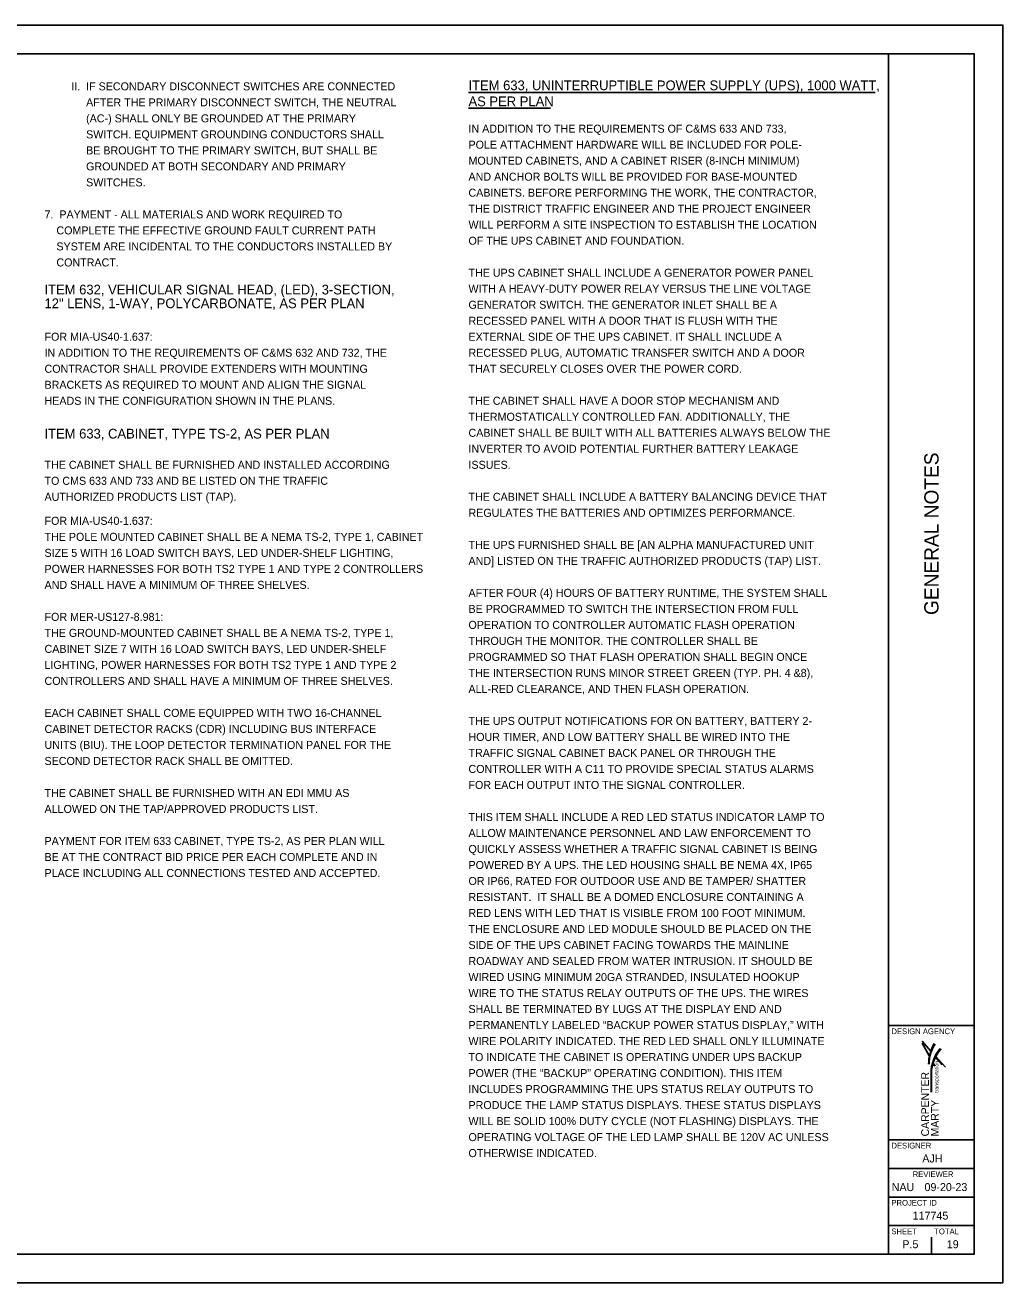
# Model space of a CAD drawing. Extents: x -57 to 92, y -15 to 47.
# Drawn here: x 75.2 to 92.31, y 25.1 to 47.1 of the extents above; entities that cross this region are included whole.
import ezdxf

# ---------------------------------------------------------------- set-up
doc = ezdxf.new("R2010")
doc.units = 0
for name, color, linetype in [('SH_Border', 7, 'Continuous'), ('SH_Cut_Line', 7, 'Continuous'), ('SH_Data', 7, 'Continuous'), ('SH_Text', 7, 'Continuous')]:
    doc.layers.add(name, color=color, linetype=linetype)

msp = doc.modelspace()

# ---------------------------------------------------------------- linework, layer by layer
at = {"layer": 'SH_Border'}
for p, q in [((90.307, 25.604), (90.307, 46.604)), ((90.307, 29.604), (91.807, 29.604)), ((90.307, 27.604), (91.807, 27.604)), ((90.307, 27.104), (91.807, 27.104)), ((90.307, 26.604), (91.807, 26.604)), ((90.307, 26.104), (91.807, 26.104))]:
    msp.add_line(p, q, dxfattribs=at)
msp.add_lwpolyline([(59.807, 46.604), (91.807, 46.604), (91.807, 25.604), (59.807, 25.604)], close=True, dxfattribs=at)
at = {"layer": 'SH_Cut_Line'}
msp.add_lwpolyline([(58.307, 25.104), (92.307, 25.104), (92.307, 47.104), (58.307, 47.104)], close=True, dxfattribs=at)
at = {"layer": 'SH_Data'}
for p, q in [((91.057, 28.604), (91.057, 28.604)), ((90.682, 25.779), (90.682, 25.779)), ((91.057, 25.604), (91.057, 25.904))]:
    msp.add_line(p, q, dxfattribs=at)
at = {"layer": 'SH_Text'}
for p, q in [((82.955, 45.923), (90.07, 45.923)), ((82.955, 45.652), (84.391, 45.652)), ((91.016, 29.079), (90.897, 29.295)), ((91.247, 28.915), (91.13, 29.054)), ((91.135, 29.064), (91.301, 28.879)), ((91.106, 28.903), (91.085, 28.943)), ((91.116, 28.896), (91.087, 28.949)), ((91.05, 28.44), (91.05, 28.767)), ((91.057, 28.44), (91.057, 28.767))]:
    msp.add_line(p, q, dxfattribs=at)
for points in [[(91.042, 29.167), (90.897, 29.329)], [(90.897, 29.329), (91.039, 29.161)], [(91.016, 29.079), (90.897, 29.295)], [(90.897, 29.294), (91.015, 29.074)]]:
    msp.add_lwpolyline(points, dxfattribs=at)
for centre, radius, start, end in [((91.728, 28.923), 0.721, 149.5704, 179.5529), ((91.669, 28.924), 0.654, 147.1423, 179.6525), ((91.721, 28.767), 0.671, 139.2898, 180.0106), ((91.729, 28.751), 0.672, 138.5126, 178.6075)]:
    msp.add_arc(centre, radius, start, end, dxfattribs=at)

# ---------------------------------------------------------------- texts
at = {"layer": 'SH_Data'}
msp.add_text('GENERAL NOTES', height=0.25, rotation=90, dxfattribs=at).set_placement((91.182, 36.786))
for s, height, p in [('DESIGN AGENCY', 0.1, (90.357, 29.454)), ('DESIGNER', 0.1, (90.357, 27.454)), ('AJH', 0.14, (90.897, 27.209)), ('NAU', 0.14, (90.362, 26.709)), ('REVIEWER', 0.1, (90.729, 26.954)), ('09-20-23', 0.14, (90.936, 26.709)), ('PROJECT ID', 0.1, (90.357, 26.454)), ('117745', 0.14, (90.728, 26.209)), ('SHEET', 0.1, (90.357, 25.954)), ('TOTAL', 0.1, (91.107, 25.954)), ('P.5', 0.14, (90.548, 25.709)), ('19', 0.14, (91.326, 25.709))]:
    msp.add_text(s, height=height, dxfattribs=at).set_placement(p)
at = {"layer": 'SH_Text'}
for s, height, p in [('         II.  IF SECONDARY DISCONNECT SWITCHES ARE CONNECTED', 0.14, (75.535, 45.963)), ('ITEM 633, UNINTERRUPTIBLE POWER SUPPLY (UPS), 1000 WATT,', 0.17, (82.955, 45.966)), ('              AFTER THE PRIMARY DISCONNECT SWITCH, THE NEUTRAL', 0.14, (75.535, 45.683)), ('AS PER PLAN', 0.17, (82.955, 45.686)), ('              (AC-) SHALL ONLY BE GROUNDED AT THE PRIMARY', 0.14, (75.535, 45.403)), ('IN ADDITION TO THE REQUIREMENTS OF C&MS 633 AND 733, ', 0.14, (82.955, 45.223)), ('              SWITCH. EQUIPMENT GROUNDING CONDUCTORS SHALL', 0.14, (75.535, 45.123)), ('              BE BROUGHT TO THE PRIMARY SWITCH, BUT SHALL BE', 0.14, (75.535, 44.843)), ('POLE ATTACHMENT HARDWARE WILL BE INCLUDED FOR POLE-', 0.14, (82.955, 44.943)), ('              GROUNDED AT BOTH SECONDARY AND PRIMARY', 0.14, (75.535, 44.563)), ('MOUNTED CABINETS, AND A CABINET RISER (8-INCH MINIMUM) ', 0.14, (82.955, 44.663)), ('AND ANCHOR BOLTS WILL BE PROVIDED FOR BASE-MOUNTED ', 0.14, (82.955, 44.383)), ('              SWITCHES.', 0.14, (75.535, 44.283)), ('CABINETS. BEFORE PERFORMING THE WORK, THE CONTRACTOR, ', 0.14, (82.955, 44.103)), ('7.  PAYMENT - ALL MATERIALS AND WORK REQUIRED TO', 0.14, (75.535, 43.723)), ('THE DISTRICT TRAFFIC ENGINEER AND THE PROJECT ENGINEER ', 0.14, (82.955, 43.823)), ('    COMPLETE THE EFFECTIVE GROUND FAULT CURRENT PATH', 0.14, (75.535, 43.443)), ('WILL PERFORM A SITE INSPECTION TO ESTABLISH THE LOCATION ', 0.14, (82.955, 43.543)), ('OF THE UPS CABINET AND FOUNDATION.', 0.14, (82.955, 43.263)), ('    SYSTEM ARE INCIDENTAL TO THE CONDUCTORS INSTALLED BY', 0.14, (75.535, 43.163)), ('    CONTRACT.', 0.14, (75.535, 42.883)), ('THE UPS CABINET SHALL INCLUDE A GENERATOR POWER PANEL ', 0.14, (82.955, 42.703)), ('ITEM 632, VEHICULAR SIGNAL HEAD, (LED), 3-SECTION, ', 0.17, (75.535, 42.393)), ('WITH A HEAVY-DUTY POWER RELAY VERSUS THE LINE VOLTAGE ', 0.14, (82.955, 42.423)), ('12" LENS, 1-WAY, POLYCARBONATE, AS PER PLAN', 0.17, (75.535, 42.153)), ('GENERATOR SWITCH. THE GENERATOR INLET SHALL BE A ', 0.14, (82.955, 42.143)), ('RECESSED PANEL WITH A DOOR THAT IS FLUSH WITH THE ', 0.14, (82.955, 41.863)), ('FOR MIA-US40-1.637:', 0.14, (75.535, 41.583)), ('EXTERNAL SIDE OF THE UPS CABINET. IT SHALL INCLUDE A ', 0.14, (82.955, 41.583)), ('IN ADDITION TO THE REQUIREMENTS OF C&MS 632 AND 732, THE ', 0.14, (75.535, 41.303)), ('RECESSED PLUG, AUTOMATIC TRANSFER SWITCH AND A DOOR ', 0.14, (82.955, 41.303)), ('CONTRACTOR SHALL PROVIDE EXTENDERS WITH MOUNTING ', 0.14, (75.535, 41.023)), ('THAT SECURELY CLOSES OVER THE POWER CORD.', 0.14, (82.955, 41.023)), ('BRACKETS AS REQUIRED TO MOUNT AND ALIGN THE SIGNAL ', 0.14, (75.535, 40.743)), ('HEADS IN THE CONFIGURATION SHOWN IN THE PLANS. ', 0.14, (75.535, 40.463)), ('THE CABINET SHALL HAVE A DOOR STOP MECHANISM AND ', 0.14, (82.955, 40.463)), ('THERMOSTATICALLY CONTROLLED FAN. ADDITIONALLY, THE ', 0.14, (82.955, 40.183)), ('ITEM 633, CABINET, TYPE TS-2, AS PER PLAN', 0.17, (75.535, 39.873)), ('CABINET SHALL BE BUILT WITH ALL BATTERIES ALWAYS BELOW THE ', 0.14, (82.955, 39.903)), ('INVERTER TO AVOID POTENTIAL FURTHER BATTERY LEAKAGE ', 0.14, (82.955, 39.623)), ('THE CABINET SHALL BE FURNISHED AND INSTALLED ACCORDING', 0.14, (75.535, 39.343)), ('ISSUES.', 0.14, (82.955, 39.343)), ('TO CMS 633 AND 733 AND BE LISTED ON THE TRAFFIC', 0.14, (75.535, 39.063)), ('AUTHORIZED PRODUCTS LIST (TAP).', 0.14, (75.535, 38.783)), ('THE CABINET SHALL INCLUDE A BATTERY BALANCING DEVICE THAT ', 0.14, (82.955, 38.783)), ('FOR MIA-US40-1.637:', 0.14, (75.535, 38.363)), ('REGULATES THE BATTERIES AND OPTIMIZES PERFORMANCE. ', 0.14, (82.955, 38.503)), ('THE POLE MOUNTED CABINET SHALL BE A NEMA TS-2, TYPE 1, CABINET ', 0.14, (75.535, 38.083)), ('THE UPS FURNISHED SHALL BE [AN ALPHA MANUFACTURED UNIT ', 0.14, (82.955, 37.943)), ('SIZE 5 WITH 16 LOAD SWITCH BAYS, LED UNDER-SHELF LIGHTING, ', 0.14, (75.535, 37.803)), ('POWER HARNESSES FOR BOTH TS2 TYPE 1 AND TYPE 2 CONTROLLERS ', 0.14, (75.535, 37.523)), ('AND] LISTED ON THE TRAFFIC AUTHORIZED PRODUCTS (TAP) LIST.', 0.14, (82.955, 37.663)), ('AND SHALL HAVE A MINIMUM OF THREE SHELVES. ', 0.14, (75.535, 37.243)), ('AFTER FOUR (4) HOURS OF BATTERY RUNTIME, THE SYSTEM SHALL ', 0.14, (82.955, 37.103)), ('BE PROGRAMMED TO SWITCH THE INTERSECTION FROM FULL ', 0.14, (82.955, 36.823)), ('FOR MER-US127-8.981:', 0.14, (75.535, 36.683)), ('THE GROUND-MOUNTED CABINET SHALL BE A NEMA TS-2, TYPE 1,', 0.14, (75.535, 36.403)), ('OPERATION TO CONTROLLER AUTOMATIC FLASH OPERATION ', 0.14, (82.955, 36.543)), ('THROUGH THE MONITOR. THE CONTROLLER SHALL BE ', 0.14, (82.955, 36.263)), ('CABINET SIZE 7 WITH 16 LOAD SWITCH BAYS, LED UNDER-SHELF', 0.14, (75.535, 36.123)), ('PROGRAMMED SO THAT FLASH OPERATION SHALL BEGIN ONCE ', 0.14, (82.955, 35.983)), ('LIGHTING, POWER HARNESSES FOR BOTH TS2 TYPE 1 AND TYPE 2', 0.14, (75.535, 35.843)), ('CONTROLLERS AND SHALL HAVE A MINIMUM OF THREE SHELVES.', 0.14, (75.535, 35.563)), ('THE INTERSECTION RUNS MINOR STREET GREEN (TYP. PH. 4 &8), ', 0.14, (82.955, 35.703)), ('ALL-RED CLEARANCE, AND THEN FLASH OPERATION. ', 0.14, (82.955, 35.423)), ('EACH CABINET SHALL COME EQUIPPED WITH TWO 16-CHANNEL', 0.14, (75.535, 35.003)), ('THE UPS OUTPUT NOTIFICATIONS FOR ON BATTERY, BATTERY 2-', 0.14, (82.955, 34.863)), ('CABINET DETECTOR RACKS (CDR) INCLUDING BUS INTERFACE', 0.14, (75.535, 34.723)), ('UNITS (BIU). THE LOOP DETECTOR TERMINATION PANEL FOR THE', 0.14, (75.535, 34.443)), ('HOUR TIMER, AND LOW BATTERY SHALL BE WIRED INTO THE ', 0.14, (82.955, 34.583)), ('TRAFFIC SIGNAL CABINET BACK PANEL OR THROUGH THE ', 0.14, (82.955, 34.303)), ('SECOND DETECTOR RACK SHALL BE OMITTED.', 0.14, (75.535, 34.163)), ('CONTROLLER WITH A C11 TO PROVIDE SPECIAL STATUS ALARMS ', 0.14, (82.955, 34.023)), ('FOR EACH OUTPUT INTO THE SIGNAL CONTROLLER. ', 0.14, (82.955, 33.743)), ('THE CABINET SHALL BE FURNISHED WITH AN EDI MMU AS', 0.14, (75.535, 33.603)), ('ALLOWED ON THE TAP/APPROVED PRODUCTS LIST.', 0.14, (75.535, 33.323)), ('THIS ITEM SHALL INCLUDE A RED LED STATUS INDICATOR LAMP TO ', 0.14, (82.955, 33.183)), ('ALLOW MAINTENANCE PERSONNEL AND LAW ENFORCEMENT TO ', 0.14, (82.955, 32.903)), ('PAYMENT FOR ITEM 633 CABINET, TYPE TS-2, AS PER PLAN WILL', 0.14, (75.535, 32.763)), ('BE AT THE CONTRACT BID PRICE PER EACH COMPLETE AND IN', 0.14, (75.535, 32.483)), ('QUICKLY ASSESS WHETHER A TRAFFIC SIGNAL CABINET IS BEING ', 0.14, (82.955, 32.623)), ('PLACE INCLUDING ALL CONNECTIONS TESTED AND ACCEPTED.', 0.14, (75.535, 32.203)), ('POWERED BY A UPS. THE LED HOUSING SHALL BE NEMA 4X, IP65 ', 0.14, (82.955, 32.343)), ('OR IP66, RATED FOR OUTDOOR USE AND BE TAMPER/ SHATTER ', 0.14, (82.955, 32.063)), ('RESISTANT.  IT SHALL BE A DOMED ENCLOSURE CONTAINING A ', 0.14, (82.955, 31.783)), ('RED LENS WITH LED THAT IS VISIBLE FROM 100 FOOT MINIMUM. ', 0.14, (82.955, 31.503)), ('THE ENCLOSURE AND LED MODULE SHOULD BE PLACED ON THE ', 0.14, (82.955, 31.223)), ('SIDE OF THE UPS CABINET FACING TOWARDS THE MAINLINE ', 0.14, (82.955, 30.943)), ('ROADWAY AND SEALED FROM WATER INTRUSION. IT SHOULD BE ', 0.14, (82.955, 30.663)), ('WIRED USING MINIMUM 20GA STRANDED, INSULATED HOOKUP ', 0.14, (82.955, 30.383)), ('WIRE TO THE STATUS RELAY OUTPUTS OF THE UPS. THE WIRES ', 0.14, (82.955, 30.103)), ('SHALL BE TERMINATED BY LUGS AT THE DISPLAY END AND ', 0.14, (82.955, 29.823)), ('PERMANENTLY LABELED “BACKUP POWER STATUS DISPLAY,” WITH ', 0.14, (82.955, 29.543)), ('WIRE POLARITY INDICATED. THE RED LED SHALL ONLY ILLUMINATE ', 0.14, (82.955, 29.263)), ('TO INDICATE THE CABINET IS OPERATING UNDER UPS BACKUP ', 0.14, (82.955, 28.983)), ('POWER (THE “BACKUP” OPERATING CONDITION). THIS ITEM ', 0.14, (82.955, 28.703)), ('INCLUDES PROGRAMMING THE UPS STATUS RELAY OUTPUTS TO ', 0.14, (82.955, 28.423)), ('PRODUCE THE LAMP STATUS DISPLAYS. THESE STATUS DISPLAYS ', 0.14, (82.955, 28.143)), ('WILL BE SOLID 100% DUTY CYCLE (NOT FLASHING) DISPLAYS. THE ', 0.14, (82.955, 27.863)), ('OPERATING VOLTAGE OF THE LED LAMP SHALL BE 120V AC UNLESS ', 0.14, (82.955, 27.583)), ('OTHERWISE INDICATED.', 0.14, (82.955, 27.303))]:
    msp.add_text(s, height=height, dxfattribs=at).set_placement(p)
for s, height, p in [('transportation', 0.06649, (91.18, 28.427)), ('CARPENTER ', 0.1367, (91.015, 27.665)), ('MARTY', 0.1367, (91.186, 27.665))]:
    msp.add_text(s, height=height, rotation=90, dxfattribs=at).set_placement(p)

doc.saveas('drawing.dxf')
